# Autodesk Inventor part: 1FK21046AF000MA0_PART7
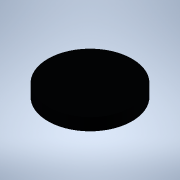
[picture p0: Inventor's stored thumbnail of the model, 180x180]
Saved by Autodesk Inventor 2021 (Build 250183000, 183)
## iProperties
Created: 2025-04
Part Number: 1FK21046AF000MA0_PART7
Material: Generic
Catalog Web Link: www.3dfindit.com
Description: -Servo synchronous motor
Document SubType Name: Modeling
Designer: psAdmin
Mass: 0.299142 g
Surface Area: 3.8585 cm^2
Volume: 0.299142 cm^3
Density: 1 g/cm^3
Appearance: PSOLRGB-38-46-56
Category: PARTsolutions
Title: 1FK21046AF000MA0_PART7
Author: Cadenas PARTsolutions
Comments: Servo synchronous motor
Sending System: PARTsolutions
Preprocessor: ST-DEVELOPER v19.3
PSOL_IDENT_0: {$CADENAS_DATA/23d-libs/siemens_ag/_cat_/1c/1f/1fk21046af000ma0.prj},213 {VTYP=3D},{NB=1FK21046AF000
PSOL_IDENT_1: MA0_PART7},{LINA=1FK21046AF000MA0_PART7},{NN=1FK21046AF000MA0_PART7},{NOPRJ=TRUE},{DATE=19.08.2025 1
PSOL_IDENT_2: 4:00:28},{GEOMDATE=30.07.2025 02:02:08},{VERSION=},{LINEID=10},{WBVAR=},{WBNUMERIC=}  {NB=1FK21046AF
PSOL_IDENT_3: 000MA0_PART7},{LINA=1FK21046AF000MA0_PART7},{KT=DUMMY},{PREVIEW=../../../_pool_/cb/72/p_d211_xx_0043
PSOL_IDENT_4: 4j.png},{DESCSHORT=SIMOTICS S-1FK2 HD, SINAMICS S210 3AC 400V-480V, 3.2 Nm, 3000 rpm},{DESCLONG=SIMO
PSOL_IDENT_5: TICS S-1FK2 HD servo motor M0=3.2 Nm; PN = 1 kW at nN=3000 rpm (380-480 V); PN = 0.5 kW at nN=1500 r
PSOL_IDENT_6: pm (200-240 V); degree of protection IP64; cylindrical shaft D19x40mm; absolute encoder 22-bit + 12-
PSOL_IDENT_7: bit multiturn (encoder AM22DQC); with OCC interface; plug size M17, rotatable; SIMOTICS S-1FK2 servo
PSOL_IDENT_8: motorfor a wide range of uses in industrial environments. SIMOTICS S‑1FK2 servomotors are compact sy
PSOL_IDENT_9: nchronous motors with a high dynamic performance that set themselves apart as a result of their high
PSOL_IDENT_10: power density, degree of protection and overload capability. The motors are available in two varian
PSOL_IDENT_11: ts: as High Dynamic variant (highest dynamic performance as a result of the low intrinsic moment of
PSOL_IDENT_12: inertia for applications demanding a high dynamic performance with low moved masses) - and as Compac
PSOL_IDENT_13: t variant (precise and stable closed-loop control for medium up to large moved masses as a result of
PSOL_IDENT_14: a medium intrinsic moment of inertia). SIMOTICSS‑1FK2 servomotors fully exploit their strengths in
PSOL_IDENT_15: a system with the SINAMICSS210 frequency converter and simple connection using the one cable connect
PSOL_IDENT_16: ion (OCC). Advantages include the short control and positioning times, fast and precise correction o
PSOL_IDENT_17: f disturbing quantities as well as stable control with a high dynamic performance. The servo motors
PSOL_IDENT_18: can be configured to address a wide range of requirements. For example with and without holding brak
PSOL_IDENT_19: e, IP64 or IP65 degree of protection, singleturn or multiturn absolute encoders - to name just a few
PSOL_IDENT_20: . Further, the servomotors are available in different shaft heights extending from 20 to 100. A shaf
PSOL_IDENT_21: t sealing ring is available to achieve an IP65 degree of protection and for subsequent mounting at t
PSOL_IDENT_22: he motor or as spare part. SIMOTICS - the optimum motor for each and every motion control applicatio
PSOL_IDENT_23: n.},{INTNO=195125049666},{SUPPLIERALTNO=1FK2104-6AF00-0MA0},{MANUID=1FK21046AF000MA0},{MANUNAME=Siem
PSOL_IDENT_24: ens},{MANUTYPEDESC=Synchronous motor 1FK2-HD 3.2 NM},{AAU732=SIMOTICS},{AAO057=S-1FK2},{AAU734=SIMOT
PSOL_IDENT_25: ICS S-1FK2 HD servo motor M0=3.2 Nm; PN = 1 kW at nN=3000 rpm (380-480 V); PN = 0.5 kW at nN=1500 rp
PSOL_IDENT_26: m (200-240 V); degree of protection IP64; cylindrical shaft D19x40mm; absolute encoder 22-bit + 12-b
PSOL_IDENT_27: it multiturn (encoder AM22DQC); with OCC interface; plug size M17, rotatable;},{AAW338=Synchronous m
PSOL_IDENT_28: otor 1FK2-HD 3.2 NM},{AAO742=SIMOTICS},{AAO663=4042948694374},{NOCUPEROU=1},{PRICEQUANTITY=1},{QUANT
PSOL_IDENT_29: ITYMIN=1},{QUANTITYINT=1},{CTN=85015220},{COO=DE},{AAO676=1FK2104-6AF00-0MA0},{AAO677=Siemens AG},{O
PSOL_IDENT_30: RDERUNIT=C62},{CONTENTUNIT=C62}
NB: 1FK21046AF000MA0_PART7
NT: Servo synchronous motor
NBSYN: $MANUID._PART7
LINA: 1FK21046AF000MA0_PART7
CATALOG: SIEMENS
PREVIEW: ../../../_pool_/cb/72/p_d211_xx_00434j.png
DESCSHORT: SIMOTICS S-1FK2 HD, SINAMICS S210 3AC 400V-480V, 3.2 Nm, 3000 rpm
DESCLONG: SIMOTICS S-1FK2 HD servo motor M0=3.2 Nm; PN = 1 kW at nN=3000 rpm (380-480 V); PN = 0.5 kW at nN=1500 rpm (200-240 V); degree of protection IP64; cylindrical s
INTNO: 195125049666
SUPPLIERALTNO: 1FK2104-6AF00-0MA0
MANUID: 1FK21046AF000MA0
MANUNAME: Siemens
MANUTYPEDESC: Synchronous motor 1FK2-HD 3.2 NM
AAU732: SIMOTICS
AAO057: S-1FK2
AAU734: SIMOTICS S-1FK2 HD servo motor M0=3.2 Nm; PN = 1 kW at nN=3000 rpm (380-480 V); PN = 0.5 kW at nN=1500 rpm (200-240 V); degree of protection IP64; cylindrical s
AAW338: Synchronous motor 1FK2-HD 3.2 NM
AAO742: SIMOTICS
AAO663: 4042948694374.0
NOCUPEROU: 1
PRICEQUANTITY: 1
QUANTITYMIN: 1
QUANTITYINT: 1
CTN: 85015220
COO: DE
ARTICLENO: 1FK21046AF000MA0_PART7
BOMINFO: 1FK21046AF000MA0_PART7
CREATOR: CADENAS GmbH
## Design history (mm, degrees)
feature "2025_04_17_15_39_11_0378"
body "Solid1"
